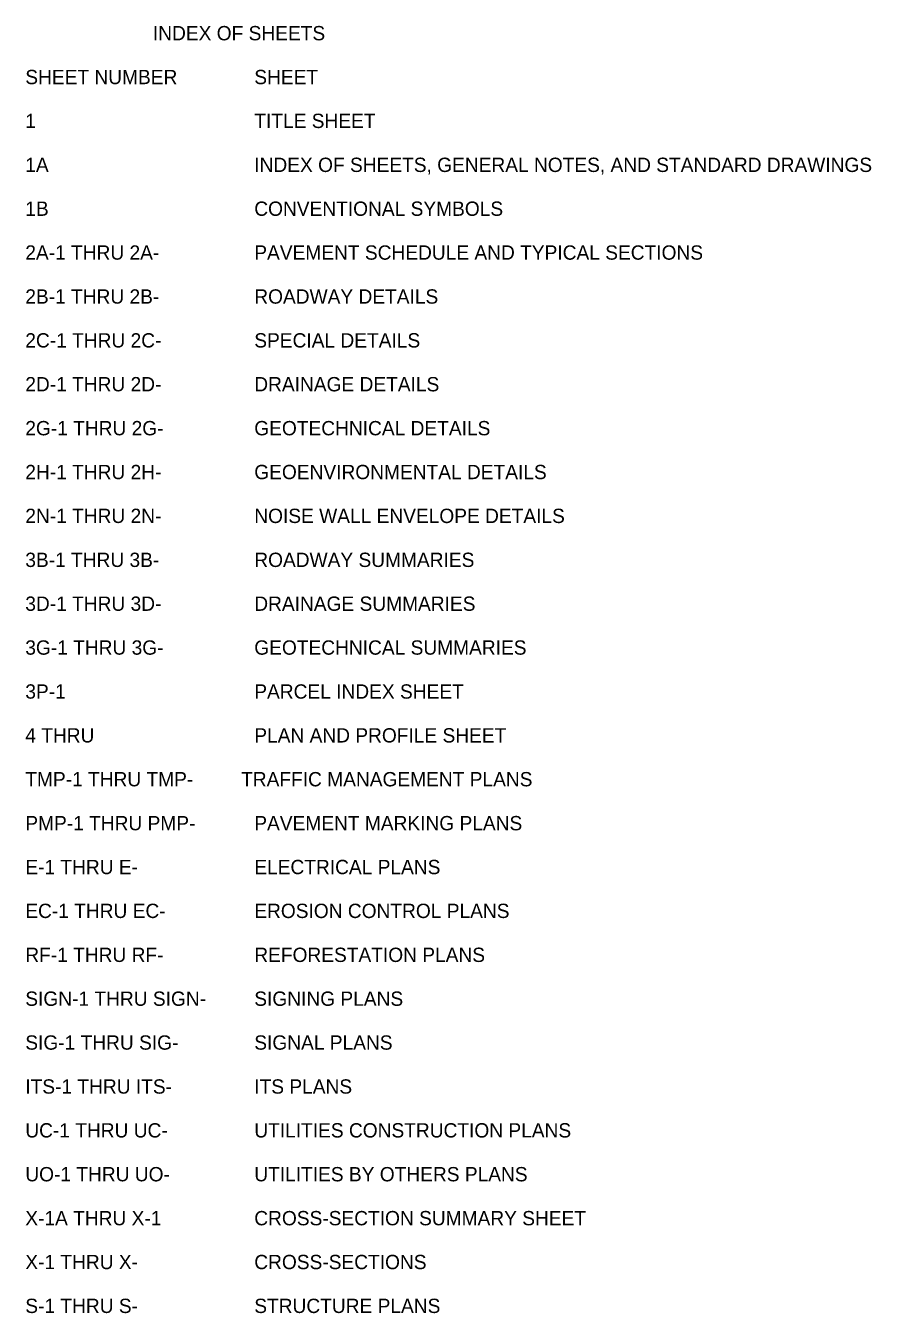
# Model space of a CAD drawing. Extents: x 1844463.5 to 1844493.8, y 671542 to 671578.6.
# Drawn here: x 1844474.41 to 1844481.8, y 671567.38 to 671578.63 of the extents above; entities that cross this region are included whole.
import ezdxf

# ---------------------------------------------------------------- set-up
doc = ezdxf.new("R2010")
doc.units = 0
doc.layers.add('Sheet_Data_Text_CELL', color=7, linetype='Continuous')

msp = doc.modelspace()

# ---------------------------------------------------------------- texts
at = {"layer": 'Sheet_Data_Text_CELL'}
for s, p in [('                        INDEX OF SHEETS ', (1844474.407, 671578.499)), ('SHEET NUMBER', (1844474.407, 671578.116)), ('SHEET   ', (1844476.407, 671578.116)), ('1                       ', (1844474.407, 671577.733)), ('TITLE SHEET', (1844476.407, 671577.733)), ('1A                      ', (1844474.407, 671577.349)), ('INDEX OF SHEETS, GENERAL NOTES, AND STANDARD DRAWINGS', (1844476.407, 671577.349)), ('1B                      ', (1844474.407, 671576.966)), ('CONVENTIONAL SYMBOLS', (1844476.407, 671576.966)), ('2A-1 THRU 2A-           ', (1844474.407, 671576.583)), ('PAVEMENT SCHEDULE AND TYPICAL SECTIONS', (1844476.407, 671576.583)), ('2B-1 THRU 2B-           ', (1844474.407, 671576.199)), ('ROADWAY DETAILS', (1844476.407, 671576.199)), ('2C-1 THRU 2C-           ', (1844474.407, 671575.816)), ('SPECIAL DETAILS', (1844476.407, 671575.816)), ('2D-1 THRU 2D-           ', (1844474.407, 671575.433)), ('DRAINAGE DETAILS', (1844476.407, 671575.433)), ('2G-1 THRU 2G-           ', (1844474.407, 671575.049)), ('GEOTECHNICAL DETAILS', (1844476.407, 671575.049)), ('2H-1 THRU 2H-           ', (1844474.407, 671574.666)), ('GEOENVIRONMENTAL DETAILS', (1844476.407, 671574.666)), ('2N-1 THRU 2N-           ', (1844474.407, 671574.283)), ('NOISE WALL ENVELOPE DETAILS', (1844476.407, 671574.283)), ('3B-1 THRU 3B-           ', (1844474.407, 671573.899)), ('ROADWAY SUMMARIES', (1844476.407, 671573.899)), ('3D-1 THRU 3D-           ', (1844474.407, 671573.516)), ('DRAINAGE SUMMARIES', (1844476.407, 671573.516)), ('3G-1 THRU 3G-           ', (1844474.407, 671573.133)), ('GEOTECHNICAL SUMMARIES', (1844476.407, 671573.133)), ('3P-1                    ', (1844474.407, 671572.749)), ('PARCEL INDEX SHEET', (1844476.407, 671572.749)), ('4 THRU                  ', (1844474.407, 671572.366)), ('PLAN AND PROFILE SHEET', (1844476.407, 671572.366)), ('TMP-1 THRU TMP-         TRAFFIC MANAGEMENT PLANS', (1844474.407, 671571.983)), ('PMP-1 THRU PMP-     ', (1844474.407, 671571.599)), ('PAVEMENT MARKING PLANS', (1844476.407, 671571.599)), ('E-1 THRU E-             ', (1844474.407, 671571.216)), ('ELECTRICAL PLANS', (1844476.407, 671571.216)), ('EC-1 THRU EC-           ', (1844474.407, 671570.833)), ('EROSION CONTROL PLANS', (1844476.407, 671570.833)), ('RF-1 THRU RF-           ', (1844474.407, 671570.449)), ('REFORESTATION PLANS', (1844476.407, 671570.449)), ('SIGN-1 THRU SIGN-    ', (1844474.407, 671570.066)), ('SIGNING PLANS', (1844476.407, 671570.066)), ('SIG-1 THRU SIG-         ', (1844474.407, 671569.683)), ('SIGNAL PLANS', (1844476.407, 671569.683)), ('ITS-1 THRU ITS-         ', (1844474.407, 671569.299)), ('ITS PLANS', (1844476.407, 671569.299)), ('UC-1 THRU UC-           ', (1844474.407, 671568.916)), ('UTILITIES CONSTRUCTION PLANS', (1844476.407, 671568.916)), ('UO-1 THRU UO-           ', (1844474.407, 671568.533)), ('UTILITIES BY OTHERS PLANS', (1844476.407, 671568.533)), ('X-1A THRU X-1           ', (1844474.407, 671568.149)), ('CROSS-SECTION SUMMARY SHEET', (1844476.407, 671568.149)), ('X-1 THRU X-             ', (1844474.407, 671567.766)), ('CROSS-SECTIONS', (1844476.407, 671567.766)), ('S-1 THRU S-             ', (1844474.407, 671567.383)), ('STRUCTURE PLANS', (1844476.407, 671567.383))]:
    msp.add_text(s, height=0.125, dxfattribs=at).set_placement(p)

doc.saveas('drawing.dxf')
